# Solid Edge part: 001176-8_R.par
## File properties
Last saved by: morva
Revision: 82
Accuracy: 0.990
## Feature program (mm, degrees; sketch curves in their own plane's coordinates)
body "unnamed Body 1"
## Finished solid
Body 1: solid body, 29 faces, 76 edges, 49 vertices.
  Faces by surface: cylinder 13, cone 8, plane 8
  Edges by curve: circle 35, line 30, curve on surface 7, spline 4
Bounding box of the edges (mm): 16.201 x 15.380 x 27.561, from (433.8616, 379.4635, 130.4556) to (450.0628, 394.844, 158.0164).
Cylindrical faces by radius (mm): R2.5 x4, R3 x3, R3.5 x3, R4.5 x3
Conical faces (half-angle, radius in mm at the cone's reference point): 4.514 deg R5.75 x5, 45 deg R3.5 x3
Planar faces by outward normal: oblique 8
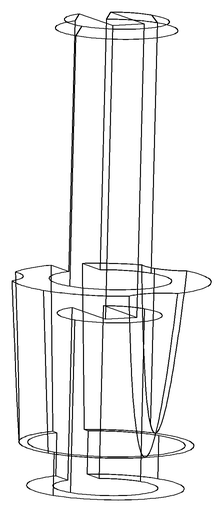
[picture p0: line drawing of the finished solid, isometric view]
